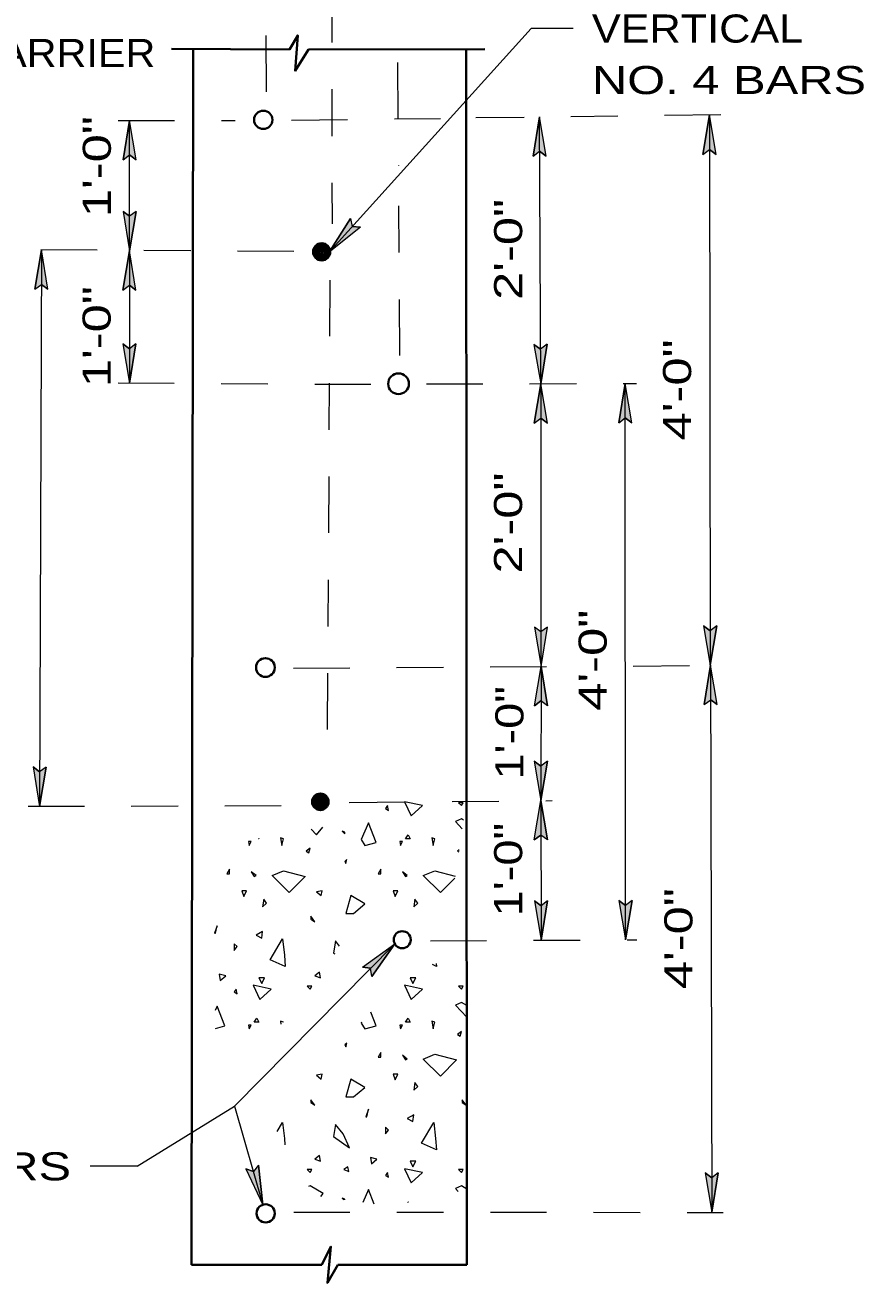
# Model space of a CAD drawing. Extents: x -11.7 to -4.5, y 8.6 to 18.8.
# Drawn here: x -6.272 to -4.481, y 10.931 to 13.617 of the extents above; entities that cross this region are included whole.
import ezdxf
from ezdxf.enums import TextEntityAlignment as Align

# ---------------------------------------------------------------- set-up
doc = ezdxf.new("R2010")
doc.units = 0
doc.header["$LTSCALE"] = 0.024
doc.linetypes.add('DOT_DASHED', pattern=[7.7, 5, -1.2, 0.3, -1.2])
for name, color, linetype, lineweight in [('1', 7, 'Continuous', 35), ('10', 7, 'Continuous', 13), ('12', 7, 'Continuous', 53), ('6', 7, 'Continuous', 13)]:
    doc.layers.add(name, color=color, linetype=linetype, lineweight=lineweight)

msp = doc.modelspace()

# ---------------------------------------------------------------- hatches: boundary and pattern name
at = {"layer": '10'}
for points in [[(-6.0345, 13.329), (-6.04867, 13.413), (-6.0625, 13.329), (-6.0485, 13.33967)], [(-5.159, 13.337), (-5.1735, 13.421), (-5.187, 13.33683), (-5.173, 13.3475)], [(-4.79617, 13.34067), (-4.81033, 13.42483), (-4.82417, 13.34067), (-4.81033, 13.35133)], [(-6.0485, 13.13483), (-6.0345, 13.21883), (-6.0485, 13.20833), (-6.0625, 13.21883)], [(-5.6225, 13.13183), (-5.57667, 13.20367), (-5.57333, 13.1865), (-5.55583, 13.18483)], [(-6.223, 13.0525), (-6.23683, 13.1365), (-6.25117, 13.0525), (-6.237, 13.063)], [(-6.06317, 13.05067), (-6.04917, 13.06117), (-6.03517, 13.05067), (-6.04917, 13.13483)], [(-6.049, 12.85183), (-6.035, 12.93583), (-6.049, 12.92533), (-6.063, 12.93583)], [(-5.1705, 12.85083), (-5.157, 12.935), (-5.171, 12.92433), (-5.185, 12.93483)], [(-5.1565, 12.76683), (-5.1705, 12.85083), (-5.1845, 12.76683), (-5.1705, 12.77733)], [(-4.97617, 12.76717), (-4.99017, 12.85117), (-5.00417, 12.76717), (-4.99017, 12.77767)], [(-5.17, 12.24717), (-5.15617, 12.33117), (-5.17017, 12.32067), (-5.18417, 12.331)], [(-4.8085, 12.2495), (-4.79467, 12.3335), (-4.8085, 12.323), (-4.82267, 12.3335)], [(-4.79367, 12.1655), (-4.80783, 12.2495), (-4.82167, 12.1655), (-4.80767, 12.176)], [(-5.17, 12.24717), (-5.15617, 12.163), (-5.17017, 12.1735), (-5.18417, 12.16317)], [(-5.1705, 11.9605), (-5.15633, 12.0445), (-5.17033, 12.034), (-5.18433, 12.0445)], [(-6.24117, 11.94817), (-6.22683, 12.03217), (-6.24083, 12.02183), (-6.25483, 12.03233)], [(-5.1705, 11.9605), (-5.15633, 11.8765), (-5.17033, 11.887), (-5.18433, 11.8765)], [(-5.16983, 11.66233), (-5.156, 11.74633), (-5.17, 11.73583), (-5.184, 11.74633)], [(-4.9895, 11.66333), (-4.9755, 11.74733), (-4.9895, 11.73683), (-5.0035, 11.74733)], [(-5.48217, 11.65467), (-5.53133, 11.58517), (-5.53383, 11.6025), (-5.55117, 11.60483)], [(-5.76383, 11.0975), (-5.7735, 11.18217), (-5.78417, 11.16817), (-5.8005, 11.1745)], [(-4.80533, 11.0815), (-4.7915, 11.16567), (-4.8055, 11.155), (-4.8195, 11.1655)]]:
    msp.add_hatch(color=256, dxfattribs=at).paths.add_polyline_path(points)

# ---------------------------------------------------------------- linework, layer by layer
at = {"layer": '1'}
for p, q in [((-5.9165, 10.96933), (-5.91317, 13.56367)), ((-5.33017, 13.563), (-5.32833, 10.96933))]:
    msp.add_line(p, q, dxfattribs=at)
for centre, radius in [((-5.76319, 13.41439), 0.01956), ((-5.63838, 13.13246), 0.01835), ((-5.63823, 13.13244), 0.0155), ((-5.63823, 13.13162), 0.01215), ((-5.63823, 13.13162), 0.00967), ((-5.63782, 13.1312), 0.00671), ((-5.63782, 13.1312), 0.00588), ((-5.63782, 13.1312), 0.00255), ((-5.4743, 12.85072), 0.02211), ((-5.75858, 12.24474), 0.01999), ((-5.6412, 11.95797), 0.01766), ((-5.64072, 11.95696), 0.0155), ((-5.6407, 11.95696), 0.01339), ((-5.64091, 11.95696), 0.01153), ((-5.64028, 11.95655), 0.01007), ((-5.63987, 11.95529), 0.00797), ((-5.63987, 11.95507), 0.0059), ((-5.64007, 11.95509), 0.00398), ((-5.63965, 11.95509), 0.00188), ((-5.46634, 11.66355), 0.01817), ((-5.758, 11.07904), 0.01936)]:
    msp.add_circle(centre, radius, dxfattribs=at)
at = {"layer": '10', "linetype": 'DOT_DASHED'}
for p, q in [((-5.7565, 13.47433), (-5.75817, 13.94817)), ((-5.48, 13.957), (-5.47467, 13.31633)), ((-5.61667, 13.69983), (-5.61633, 13.1925)), ((-6.07267, 13.413), (-5.82317, 13.41267)), ((-5.70317, 13.4135), (-5.38433, 13.4175)), ((-4.78633, 13.42483), (-5.30917, 13.41833)), ((-5.47133, 12.91083), (-5.47433, 13.27733)), ((-5.69817, 13.133), (-6.26083, 13.13667)), ((-5.62117, 13.07233), (-5.627, 12.0165)), ((-5.53317, 12.84883), (-6.073, 12.85183)), ((-5.41433, 12.85067), (-4.96617, 12.85117)), ((-4.973, 12.2475), (-4.78433, 12.2495)), ((-5.6985, 12.2435), (-5.10633, 12.24717)), ((-5.57983, 11.95683), (-5.1465, 11.9605)), ((-6.26517, 11.94833), (-5.704, 11.94983)), ((-5.40633, 11.66117), (-4.9655, 11.66333)), ((-5.698, 11.0815), (-4.78133, 11.08117))]:
    msp.add_line(p, q, dxfattribs=at)
at = {"layer": '10'}
for p, q in [((-6.0625, 13.329), (-6.04867, 13.413)), ((-6.0485, 13.13483), (-6.04867, 13.413)), ((-6.0345, 13.329), (-6.04867, 13.413)), ((-5.187, 13.33683), (-5.1735, 13.421)), ((-5.1705, 12.85083), (-5.1735, 13.421)), ((-5.159, 13.337), (-5.1735, 13.421)), ((-4.82417, 13.34067), (-4.81033, 13.42483)), ((-4.81033, 13.42483), (-4.8085, 12.2495)), ((-4.79617, 13.34067), (-4.81033, 13.42483)), ((-4.82417, 13.34067), (-4.81033, 13.35133)), ((-4.79617, 13.34067), (-4.81033, 13.35133)), ((-6.0625, 13.329), (-6.0485, 13.33967)), ((-6.0345, 13.329), (-6.0485, 13.33967)), ((-5.187, 13.33683), (-5.173, 13.3475)), ((-5.159, 13.337), (-5.173, 13.3475)), ((-6.0625, 13.21883), (-6.0485, 13.13483)), ((-6.0625, 13.21883), (-6.0485, 13.20833)), ((-6.0345, 13.21883), (-6.0485, 13.13483)), ((-6.0345, 13.21883), (-6.0485, 13.20833)), ((-5.57667, 13.20367), (-5.6225, 13.13183)), ((-5.57667, 13.20367), (-5.57333, 13.1865)), ((-5.55583, 13.18483), (-5.6225, 13.13183)), ((-5.55583, 13.18483), (-5.57333, 13.1865)), ((-6.25117, 13.0525), (-6.23683, 13.1365)), ((-6.23683, 13.1365), (-6.24117, 11.94817)), ((-6.223, 13.0525), (-6.23683, 13.1365)), ((-6.06317, 13.05067), (-6.04917, 13.13483)), ((-6.04917, 13.13483), (-6.049, 12.85183)), ((-6.03517, 13.05067), (-6.04917, 13.13483)), ((-6.25117, 13.0525), (-6.237, 13.063)), ((-6.223, 13.0525), (-6.237, 13.063)), ((-6.06317, 13.05067), (-6.04917, 13.06117)), ((-6.03517, 13.05067), (-6.04917, 13.06117)), ((-6.063, 12.93583), (-6.049, 12.85183)), ((-6.063, 12.93583), (-6.049, 12.92533)), ((-6.035, 12.93583), (-6.049, 12.85183)), ((-6.035, 12.93583), (-6.049, 12.92533)), ((-5.185, 12.93483), (-5.1705, 12.85083)), ((-5.185, 12.93483), (-5.171, 12.92433)), ((-5.157, 12.935), (-5.171, 12.92433)), ((-5.157, 12.935), (-5.1705, 12.85083)), ((-5.1845, 12.76683), (-5.1705, 12.85083)), ((-5.1705, 12.85083), (-5.17017, 12.24717)), ((-5.1565, 12.76683), (-5.1705, 12.85083)), ((-5.00417, 12.76717), (-4.99017, 12.85117)), ((-4.9895, 11.66333), (-4.99017, 12.85117)), ((-4.97617, 12.76717), (-4.99017, 12.85117)), ((-5.1845, 12.76683), (-5.1705, 12.77733)), ((-5.1565, 12.76683), (-5.1705, 12.77733)), ((-5.00417, 12.76717), (-4.99017, 12.77767)), ((-4.97617, 12.76717), (-4.99017, 12.77767)), ((-4.82267, 12.3335), (-4.8085, 12.2495)), ((-4.82267, 12.3335), (-4.8085, 12.323)), ((-4.79467, 12.3335), (-4.8085, 12.2495)), ((-4.79467, 12.3335), (-4.8085, 12.323)), ((-4.82167, 12.1655), (-4.80783, 12.2495)), ((-4.80783, 12.2495), (-4.80533, 11.0815)), ((-4.79367, 12.1655), (-4.80783, 12.2495)), ((-5.18417, 12.16317), (-5.17, 12.24717)), ((-5.15617, 12.163), (-5.17, 12.24717)), ((-5.18417, 12.16317), (-5.17017, 12.1735)), ((-5.15617, 12.163), (-5.17017, 12.1735)), ((-4.82167, 12.1655), (-4.80767, 12.176)), ((-4.79367, 12.1655), (-4.80767, 12.176)), ((-5.18433, 12.0445), (-5.1705, 11.9605)), ((-5.18433, 12.0445), (-5.17033, 12.034)), ((-5.15633, 12.0445), (-5.1705, 11.9605)), ((-5.15633, 12.0445), (-5.17033, 12.034)), ((-6.25483, 12.03233), (-6.24117, 11.94817)), ((-6.25483, 12.03233), (-6.24083, 12.02183)), ((-6.22683, 12.03217), (-6.24117, 11.94817)), ((-6.22683, 12.03217), (-6.24083, 12.02183)), ((-5.18433, 11.8765), (-5.1705, 11.9605)), ((-5.15633, 11.8765), (-5.1705, 11.9605)), ((-5.18433, 11.8765), (-5.17033, 11.887)), ((-5.15633, 11.8765), (-5.17033, 11.887)), ((-5.184, 11.74633), (-5.16983, 11.66233)), ((-5.184, 11.74633), (-5.17, 11.73583)), ((-5.156, 11.74633), (-5.17, 11.73583)), ((-5.156, 11.74633), (-5.16983, 11.66233)), ((-5.0035, 11.74733), (-4.9895, 11.66333)), ((-5.0035, 11.74733), (-4.9895, 11.73683)), ((-4.9755, 11.74733), (-4.9895, 11.66333)), ((-4.9755, 11.74733), (-4.9895, 11.73683)), ((-5.82433, 11.30833), (-5.48217, 11.65467)), ((-5.55117, 11.60483), (-5.48217, 11.65467)), ((-5.53133, 11.58517), (-5.48217, 11.65467)), ((-5.55117, 11.60483), (-5.53383, 11.6025)), ((-5.53133, 11.58517), (-5.53383, 11.6025)), ((-6.03267, 11.1795), (-5.82433, 11.30833)), ((-5.82433, 11.30833), (-5.76383, 11.0975)), ((-6.03267, 11.1795), (-6.13267, 11.1795)), ((-5.8005, 11.1745), (-5.76383, 11.0975)), ((-5.8005, 11.1745), (-5.78417, 11.16817)), ((-5.7735, 11.18217), (-5.78417, 11.16817)), ((-5.7735, 11.18217), (-5.76383, 11.0975)), ((-4.8195, 11.1655), (-4.80533, 11.0815)), ((-4.8195, 11.1655), (-4.8055, 11.155)), ((-4.7915, 11.16567), (-4.8055, 11.155)), ((-4.7915, 11.16567), (-4.80533, 11.0815))]:
    msp.add_line(p, q, dxfattribs=at)
at = {"layer": '10', "lineweight": 35}
for p, q in [((-5.63817, 10.96933), (-5.9165, 10.96933)), ((-5.32833, 10.96933), (-5.60367, 10.96933))]:
    msp.add_line(p, q, dxfattribs=at)
for points in [[(-5.95883, 13.56583), (-5.70733, 13.56467), (-5.6895, 13.5945), (-5.69517, 13.51917), (-5.66633, 13.56433), (-5.29, 13.56533)], [(-5.63817, 10.96933), (-5.61883, 11.00817), (-5.626, 10.93067), (-5.60367, 10.96933)]]:
    msp.add_lwpolyline(points, dxfattribs=at)
at = {"layer": '10'}
for points in [[(-5.10133, 13.60933), (-5.19133, 13.60933), (-5.6225, 13.13183)], [(-5.17, 12.24717), (-5.1705, 11.9605), (-5.16983, 11.66233)]]:
    msp.add_lwpolyline(points, dxfattribs=at)
for points in [[(-6.0345, 13.329), (-6.04867, 13.413), (-6.0625, 13.329), (-6.0485, 13.33967)], [(-5.159, 13.337), (-5.1735, 13.421), (-5.187, 13.33683), (-5.173, 13.3475)], [(-4.79617, 13.34067), (-4.81033, 13.42483), (-4.82417, 13.34067), (-4.81033, 13.35133)], [(-6.0485, 13.13483), (-6.0345, 13.21883), (-6.0485, 13.20833), (-6.0625, 13.21883)], [(-5.6225, 13.13183), (-5.57667, 13.20367), (-5.57333, 13.1865), (-5.55583, 13.18483)], [(-6.223, 13.0525), (-6.23683, 13.1365), (-6.25117, 13.0525), (-6.237, 13.063)], [(-6.06317, 13.05067), (-6.04917, 13.06117), (-6.03517, 13.05067), (-6.04917, 13.13483)], [(-6.049, 12.85183), (-6.035, 12.93583), (-6.049, 12.92533), (-6.063, 12.93583)], [(-5.1705, 12.85083), (-5.157, 12.935), (-5.171, 12.92433), (-5.185, 12.93483)], [(-5.1565, 12.76683), (-5.1705, 12.85083), (-5.1845, 12.76683), (-5.1705, 12.77733)], [(-4.97617, 12.76717), (-4.99017, 12.85117), (-5.00417, 12.76717), (-4.99017, 12.77767)], [(-5.17, 12.24717), (-5.15617, 12.33117), (-5.17017, 12.32067), (-5.18417, 12.331)], [(-4.8085, 12.2495), (-4.79467, 12.3335), (-4.8085, 12.323), (-4.82267, 12.3335)], [(-4.79367, 12.1655), (-4.80783, 12.2495), (-4.82167, 12.1655), (-4.80767, 12.176)], [(-5.17, 12.24717), (-5.15617, 12.163), (-5.17017, 12.1735), (-5.18417, 12.16317)], [(-5.1705, 11.9605), (-5.15633, 12.0445), (-5.17033, 12.034), (-5.18433, 12.0445)], [(-6.24117, 11.94817), (-6.22683, 12.03217), (-6.24083, 12.02183), (-6.25483, 12.03233)], [(-5.1705, 11.9605), (-5.15633, 11.8765), (-5.17033, 11.887), (-5.18433, 11.8765)], [(-5.16983, 11.66233), (-5.156, 11.74633), (-5.17, 11.73583), (-5.184, 11.74633)], [(-4.9895, 11.66333), (-4.9755, 11.74733), (-4.9895, 11.73683), (-5.0035, 11.74733)], [(-5.48217, 11.65467), (-5.53133, 11.58517), (-5.53383, 11.6025), (-5.55117, 11.60483)], [(-5.76383, 11.0975), (-5.7735, 11.18217), (-5.78417, 11.16817), (-5.8005, 11.1745)], [(-4.80533, 11.0815), (-4.7915, 11.16567), (-4.8055, 11.155), (-4.8195, 11.1655)]]:
    msp.add_lwpolyline(points, close=True, dxfattribs=at)
at = {"layer": '6'}
for points in [[(-5.46167, 11.958), (-5.44733, 11.92767), (-5.42333, 11.94983)], [(-5.3465, 11.956), (-5.34017, 11.94983), (-5.33633, 11.956)], [(-5.502, 11.9435), (-5.49583, 11.93967), (-5.49767, 11.94983)], [(-5.54617, 11.86483), (-5.52217, 11.871), (-5.5385, 11.91333), (-5.55433, 11.87733)], [(-5.79483, 11.873), (-5.793, 11.86483), (-5.78867, 11.873)], [(-5.72617, 11.88117), (-5.72383, 11.86483), (-5.72, 11.87917)], [(-5.58883, 11.89317), (-5.59467, 11.895), (-5.58883, 11.88933)], [(-5.47183, 11.873), (-5.46983, 11.86483), (-5.4655, 11.873)], [(-5.4535, 11.88733), (-5.44917, 11.87917), (-5.45933, 11.87917)], [(-5.40317, 11.88117), (-5.40067, 11.86483), (-5.39683, 11.87917)], [(-5.6715, 11.85283), (-5.66567, 11.849), (-5.66333, 11.859)], [(-5.5845, 11.8345), (-5.58883, 11.83067), (-5.5865, 11.82633)], [(-5.83517, 11.81433), (-5.841, 11.80433), (-5.83517, 11.80433)], [(-5.78233, 11.7985), (-5.7785, 11.8005), (-5.78867, 11.80867)], [(-5.72, 11.8105), (-5.67333, 11.7985), (-5.708, 11.764), (-5.7445, 11.8005)], [(-5.51217, 11.81433), (-5.51783, 11.80433), (-5.51217, 11.80433)], [(-5.45933, 11.7985), (-5.4555, 11.8005), (-5.4655, 11.80867)], [(-5.80883, 11.76783), (-5.805, 11.75583), (-5.79867, 11.76783)], [(-5.64933, 11.76583), (-5.63933, 11.75767), (-5.63733, 11.76783)], [(-5.48567, 11.76783), (-5.48183, 11.75583), (-5.47567, 11.76783)], [(-5.76217, 11.75), (-5.76467, 11.73367), (-5.7565, 11.74183)], [(-5.57067, 11.71933), (-5.54617, 11.74), (-5.5765, 11.75767), (-5.5865, 11.71933)], [(-5.43917, 11.75), (-5.4415, 11.73367), (-5.43333, 11.74183)], [(-5.66133, 11.7135), (-5.66133, 11.70733), (-5.65317, 11.7015)], [(-5.86733, 11.67717), (-5.8655, 11.67717), (-5.86167, 11.69333)], [(-5.7785, 11.67317), (-5.7665, 11.667), (-5.76467, 11.68133)], [(-5.718, 11.6305), (-5.71617, 11.6065), (-5.74833, 11.6205), (-5.72183, 11.665)], [(-5.82517, 11.655), (-5.82517, 11.64067), (-5.81883, 11.64883)], [(-5.85733, 11.59017), (-5.85533, 11.57633), (-5.84333, 11.58633)], [(-5.77233, 11.582), (-5.7665, 11.57), (-5.76033, 11.582)], [(-5.64317, 11.5945), (-5.65317, 11.58633), (-5.64117, 11.582)], [(-5.44917, 11.582), (-5.4435, 11.57), (-5.43717, 11.582)], [(-5.82517, 11.55183), (-5.81883, 11.548), (-5.82083, 11.558)], [(-5.78483, 11.56617), (-5.77033, 11.536), (-5.74633, 11.558)], [(-5.6695, 11.56433), (-5.66333, 11.558), (-5.6595, 11.56433)], [(-5.46167, 11.56617), (-5.44733, 11.536), (-5.42333, 11.558)], [(-5.3465, 11.56433), (-5.34017, 11.558), (-5.33633, 11.56433)], [(-5.79483, 11.48117), (-5.793, 11.473), (-5.78867, 11.48117)], [(-5.77667, 11.49567), (-5.77233, 11.4875), (-5.78233, 11.4875)], [(-5.47183, 11.48117), (-5.46983, 11.473), (-5.4655, 11.48117)], [(-5.4535, 11.49567), (-5.44917, 11.4875), (-5.45933, 11.4875)], [(-5.40317, 11.48933), (-5.40067, 11.473), (-5.39683, 11.4875)], [(-5.5845, 11.44283), (-5.58883, 11.439), (-5.5865, 11.43467)], [(-5.34833, 11.461), (-5.34267, 11.45717), (-5.34017, 11.46733)], [(-5.51217, 11.42267), (-5.51783, 11.4125), (-5.51217, 11.4125)], [(-5.45933, 11.40683), (-5.4555, 11.40867), (-5.4655, 11.41683)], [(-5.39683, 11.41883), (-5.35033, 11.40683), (-5.38483, 11.37217), (-5.42133, 11.40867)], [(-5.64933, 11.37417), (-5.63933, 11.366), (-5.63733, 11.376)], [(-5.57067, 11.32767), (-5.54617, 11.34817), (-5.5765, 11.366), (-5.5865, 11.32767)], [(-5.48567, 11.376), (-5.48183, 11.364), (-5.47567, 11.376)], [(-5.43917, 11.35833), (-5.4415, 11.342), (-5.43333, 11.35017)], [(-5.66133, 11.32183), (-5.66133, 11.31567), (-5.65317, 11.30983)], [(-5.33833, 11.32183), (-5.33833, 11.31567), (-5.33017, 11.30983)], [(-5.54433, 11.28533), (-5.54233, 11.28533), (-5.5385, 11.30167)], [(-5.4555, 11.2815), (-5.4435, 11.27533), (-5.4415, 11.28967)], [(-5.609, 11.269), (-5.61283, 11.24317), (-5.57883, 11.21867), (-5.59267, 11.24883)], [(-5.502, 11.26333), (-5.502, 11.24883), (-5.49583, 11.257)], [(-5.395, 11.23883), (-5.393, 11.21483), (-5.42517, 11.22867), (-5.39883, 11.27333)], [(-5.64317, 11.20283), (-5.65317, 11.19467), (-5.64117, 11.19033)], [(-5.59083, 11.1725), (-5.58067, 11.16817), (-5.58267, 11.17833)], [(-5.53417, 11.1985), (-5.53233, 11.1845), (-5.52033, 11.19467)], [(-5.46167, 11.1745), (-5.44733, 11.14417), (-5.42333, 11.16633)], [(-5.44917, 11.19033), (-5.4435, 11.17833), (-5.43717, 11.19033)], [(-5.6695, 11.1725), (-5.66333, 11.16633), (-5.6595, 11.1725)], [(-5.502, 11.16), (-5.49583, 11.15617), (-5.49767, 11.16633)], [(-5.3465, 11.1725), (-5.34017, 11.16633), (-5.33633, 11.1725)]]:
    msp.add_lwpolyline(points, close=True, dxfattribs=at)
for points in [[(-5.66067, 11.8995), (-5.64933, 11.88733), (-5.636, 11.904)], [(-5.33533, 11.91867), (-5.34017, 11.9215), (-5.35267, 11.91567), (-5.33817, 11.9)], [(-5.77233, 11.87933), (-5.77233, 11.87917), (-5.77317, 11.87917)], [(-5.345, 11.8555), (-5.34833, 11.85283), (-5.3455, 11.851)], [(-5.35417, 11.79483), (-5.38483, 11.764), (-5.42133, 11.8005), (-5.39683, 11.8105), (-5.3535, 11.79933)], [(-5.60033, 11.64983), (-5.609, 11.66083), (-5.61283, 11.63483), (-5.6105, 11.633)], [(-5.39367, 11.61283), (-5.393, 11.6065), (-5.402, 11.6105)], [(-5.32833, 11.58783), (-5.33017, 11.58633), (-5.32833, 11.58567)], [(-5.32833, 11.52283), (-5.34017, 11.52967), (-5.35267, 11.524), (-5.32833, 11.49783)], [(-5.86517, 11.47417), (-5.84533, 11.47933), (-5.86167, 11.5215), (-5.86567, 11.5125)], [(-5.5535, 11.48767), (-5.55433, 11.4855), (-5.54617, 11.473), (-5.52217, 11.47933), (-5.5335, 11.5085)], [(-5.72, 11.48717), (-5.72, 11.4875), (-5.72617, 11.48933), (-5.72533, 11.48333)], [(-5.73333, 11.254), (-5.72183, 11.27333), (-5.718, 11.23883), (-5.717, 11.22533)], [(-5.32833, 11.19617), (-5.33017, 11.19467), (-5.32833, 11.194)], [(-5.64033, 11.115), (-5.635, 11.12167), (-5.66333, 11.138), (-5.6665, 11.1365)], [(-5.52667, 11.099), (-5.5385, 11.12983), (-5.5505, 11.1025)], [(-5.32833, 11.131), (-5.34017, 11.138), (-5.35267, 11.13217), (-5.34683, 11.12583)], [(-5.58883, 11.10783), (-5.58883, 11.10967), (-5.59467, 11.1115), (-5.59133, 11.10817)], [(-5.45467, 11.10233), (-5.4535, 11.10383), (-5.45283, 11.10267)]]:
    msp.add_lwpolyline(points, dxfattribs=at)

# ---------------------------------------------------------------- texts
at = {"layer": '12'}
for s, width, p in [('VERTICAL', 1.15, (-5.06133, 13.57933)), ('BARRIER', 1.1, (-6.38608, 13.52717)), ('NO. 4 BARS', 1.3, (-5.06133, 13.46933)), ('NO. 8 BARS', 1.3, (-6.75908, 11.1495))]:
    msp.add_text(s, height=0.06001, dxfattribs=dict(at, width=width)).set_placement(p)
for s, width, p in [('1\'-0"', 1.35, (-6.08858, 13.31442)), ('2\'-0"', 1.35, (-5.21017, 13.13758)), ('1\'-0"', 1.35, (-6.08908, 12.95133)), ('4\'-0"', 1.35, (-4.84942, 12.83767)), ('2\'-0"', 1.35, (-5.21033, 12.55333)), ('4\'-0"', 1.35, (-5.02983, 12.26033)), ('1\'-0"', 1.25, (-5.2075, 12.10529)), ('1\'-0"', 1.25, (-5.21017, 11.81321)), ('4\'-0"', 1.35, (-4.84658, 11.66567))]:
    msp.add_text(s, height=0.06001, rotation=90, dxfattribs=dict(at, width=width)).set_placement(p, align=Align.CENTER)

doc.saveas('drawing.dxf')
